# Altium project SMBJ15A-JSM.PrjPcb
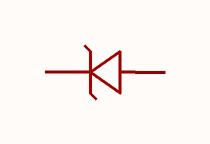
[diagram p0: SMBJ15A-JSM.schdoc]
1 sheet, 1 parts. Net scope: global (net labels, ports and power ports of the same name join across sheets).

## Sheet SMBJ15A-JSM.schdoc
size 127 x 101 mm

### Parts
D?  smbj15a-jsm  [SMB_L4.3-W3.6-LS5.3-RD]  (value not drawn)

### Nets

Not connected (* = marked no-connect by the designer): D? 1(C) 2(A)

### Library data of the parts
D? = smbj15a-jsm: 极性:单向;反向截止电压(Vrwm):15V;钳位电压:24.4V;峰值脉冲电流(Ipp):24.6A;峰值脉冲功率(Ppp):600W;击穿电压(VBR):18.5V;; Manufacturer: JSMSEMI(杰盛微); AddInBom: yes; ModelId: 314c1f1e2ff843d9bed33f9992fd5d20; ModelName: SMB_L4.32-W3.62-LS5.3-RD; ModelTransform: 208.661,142.5194,0,0,0,0,0,0,0; Polarity: 单向; Reverse Stand-Off Voltage (Vrwm): 15V; Clamping Voltage: 24.4V; Peak Pulse Current (Ipp): 24.6A; Peak Pulse Power Dissipation (Ppp): 600W; Voltage - Breakdown: 18.5V; Reverse Leakage Current (Ir): 1uA; Number of Channels: 单路; Type: TVS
